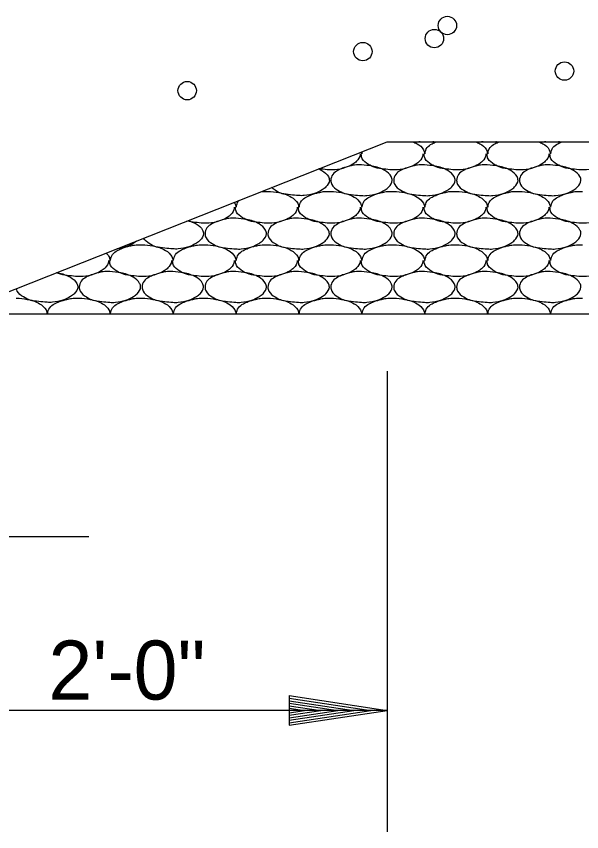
# Model space of a CAD drawing. Extents: x 3287 to 1767681, y -265 to 581440.
# Drawn here: x 3331.47 to 3342.97, y -60.82 to -44.23 of the extents above; entities that cross this region are included whole.
import ezdxf

# ---------------------------------------------------------------- set-up
doc = ezdxf.new("R2010")
doc.units = 0
doc.layers.add('Default', color=7, linetype='Continuous')

msp = doc.modelspace()

# ---------------------------------------------------------------- linework, layer by layer
at = {"layer": 'Default'}
for p, q in [((3329.016, -50.743), (3339.016, -46.785)), ((3339.016, -46.785), (3419.01, -46.785)), ((3336.461, -47.796), (3336.574, -47.795)), ((3336.574, -47.795), (3336.589, -47.795)), ((3337.854, -47.795), (3337.869, -47.795)), ((3339.133, -47.795), (3339.148, -47.795)), ((3340.413, -47.795), (3340.428, -47.795)), ((3341.693, -47.795), (3341.708, -47.795)), ((3342.973, -47.795), (3342.988, -47.795)), ((3334.014, -48.88), (3334.029, -48.88)), ((3335.294, -48.88), (3335.309, -48.88)), ((3336.574, -48.88), (3336.589, -48.88)), ((3337.854, -48.88), (3337.869, -48.88)), ((3339.133, -48.88), (3339.148, -48.88)), ((3340.413, -48.88), (3340.428, -48.88)), ((3341.693, -48.88), (3341.708, -48.88)), ((3342.973, -48.88), (3342.988, -48.88)), ((3332.734, -49.965), (3332.749, -49.965)), ((3334.014, -49.965), (3334.029, -49.965)), ((3335.294, -49.965), (3335.309, -49.965)), ((3336.574, -49.965), (3336.589, -49.965)), ((3337.854, -49.965), (3337.869, -49.965)), ((3339.133, -49.965), (3339.148, -49.965)), ((3340.413, -49.965), (3340.428, -49.965)), ((3341.693, -49.965), (3341.708, -49.965)), ((3342.973, -49.965), (3342.988, -49.965)), ((3330.174, -50.285), (3419.01, -50.285)), ((3339.016, -51.45), (3339.016, -60.817)), ((3332.947, -54.819), (3329.016, -54.819)), ((3337.018, -58.05), (3339.018, -58.35)), ((3337.018, -58.05), (3337.018, -58.65)), ((3337.018, -58.1), (3338.683, -58.35)), ((3337.018, -58.155), (3338.338, -58.35)), ((3337.018, -58.205), (3338.008, -58.35)), ((3339.016, -58.352), (3329.016, -58.352)), ((3337.018, -58.255), (3337.668, -58.35)), ((3337.018, -58.305), (3337.333, -58.35)), ((3337.018, -58.65), (3339.018, -58.35)), ((3337.018, -58.45), (3337.668, -58.35)), ((3337.018, -58.55), (3338.338, -58.35)), ((3337.018, -58.6), (3338.683, -58.35)), ((3337.018, -58.5), (3338.008, -58.35)), ((3337.018, -58.4), (3337.333, -58.35))]:
    msp.add_line(p, q, dxfattribs=at)
for centre in [(3340.24, -44.421), (3339.976, -44.686), (3338.52, -44.951), (3342.623, -45.348), (3334.946, -45.746)]:
    msp.add_circle(centre, 0.187, dxfattribs=at)
for points in [[(3339.538, -46.785), (3339.623, -46.825), (3339.753, -46.95), (3339.773, -47.025), (3339.773, -47.03)], [(3339.963, -46.785), (3339.883, -46.795), (3339.773, -46.795), (3339.656, -46.785)], [(3339.788, -47.03), (3339.788, -47.025), (3339.828, -46.905), (3339.928, -46.825), (3340.014, -46.785)], [(3340.818, -46.785), (3340.903, -46.825), (3341.033, -46.95), (3341.053, -47.025), (3341.053, -47.03)], [(3341.243, -46.785), (3341.163, -46.795), (3341.053, -46.795), (3340.936, -46.785)], [(3341.068, -47.03), (3341.068, -47.025), (3341.108, -46.905), (3341.208, -46.825), (3341.294, -46.785)], [(3342.098, -46.785), (3342.183, -46.825), (3342.313, -46.95), (3342.333, -47.025), (3342.333, -47.03)], [(3342.523, -46.785), (3342.443, -46.795), (3342.333, -46.795), (3342.216, -46.785)], [(3342.348, -47.03), (3342.348, -47.025), (3342.388, -46.905), (3342.488, -46.825), (3342.574, -46.785)], [(3338.463, -47.03), (3338.463, -47.045), (3338.393, -47.18), (3338.318, -47.24), (3338.163, -47.31), (3337.949, -47.355), (3337.854, -47.355)], [(3339.133, -47.355), (3339.113, -47.355), (3338.948, -47.34), (3338.768, -47.31), (3338.633, -47.245), (3338.508, -47.13), (3338.488, -47.045), (3338.488, -47.03)], [(3338.489, -46.993), (3338.493, -47.025), (3338.493, -47.03)], [(3338.508, -47.03), (3338.508, -47.025), (3338.513, -46.984)], [(3339.743, -47.03), (3339.743, -47.045), (3339.673, -47.18), (3339.598, -47.24), (3339.443, -47.31), (3339.228, -47.355), (3339.133, -47.355)], [(3340.413, -47.355), (3340.393, -47.355), (3340.228, -47.34), (3340.048, -47.31), (3339.913, -47.245), (3339.788, -47.13), (3339.768, -47.045), (3339.768, -47.03)], [(3341.023, -47.03), (3341.023, -47.045), (3340.953, -47.18), (3340.878, -47.24), (3340.723, -47.31), (3340.508, -47.355), (3340.413, -47.355)], [(3341.693, -47.355), (3341.673, -47.355), (3341.508, -47.34), (3341.328, -47.31), (3341.193, -47.245), (3341.068, -47.13), (3341.048, -47.045), (3341.048, -47.03)], [(3342.303, -47.03), (3342.303, -47.045), (3342.233, -47.18), (3342.158, -47.24), (3342.003, -47.31), (3341.788, -47.355), (3341.693, -47.355)], [(3342.973, -47.355), (3342.953, -47.355), (3342.788, -47.34), (3342.608, -47.31), (3342.473, -47.245), (3342.348, -47.13), (3342.328, -47.045), (3342.328, -47.03)], [(3343.583, -47.03), (3343.583, -47.045), (3343.513, -47.18), (3343.438, -47.24), (3343.283, -47.31), (3343.068, -47.355), (3342.973, -47.355)], [(3338.493, -47.255), (3338.713, -47.28), (3338.968, -47.37), (3339.098, -47.495), (3339.118, -47.57), (3339.048, -47.705), (3338.973, -47.765), (3338.818, -47.835), (3338.603, -47.88), (3338.493, -47.88), (3338.328, -47.865), (3338.148, -47.835), (3338.014, -47.77), (3337.889, -47.655), (3337.869, -47.57), (3337.909, -47.45), (3338.009, -47.37), (3338.108, -47.325), (3338.258, -47.28), (3338.353, -47.26), (3338.493, -47.255)], [(3339.773, -47.255), (3339.993, -47.28), (3340.248, -47.37), (3340.378, -47.495), (3340.398, -47.57), (3340.328, -47.705), (3340.253, -47.765), (3340.098, -47.835), (3339.883, -47.88), (3339.773, -47.88), (3339.608, -47.865), (3339.428, -47.835), (3339.293, -47.77), (3339.168, -47.655), (3339.148, -47.57), (3339.188, -47.45), (3339.288, -47.37), (3339.388, -47.325), (3339.538, -47.28), (3339.633, -47.26), (3339.773, -47.255)], [(3341.053, -47.255), (3341.273, -47.28), (3341.528, -47.37), (3341.658, -47.495), (3341.678, -47.57), (3341.608, -47.705), (3341.533, -47.765), (3341.378, -47.835), (3341.163, -47.88), (3341.053, -47.88), (3340.888, -47.865), (3340.708, -47.835), (3340.573, -47.77), (3340.448, -47.655), (3340.428, -47.57), (3340.468, -47.45), (3340.568, -47.37), (3340.668, -47.325), (3340.818, -47.28), (3340.913, -47.26), (3341.053, -47.255)], [(3342.333, -47.255), (3342.553, -47.28), (3342.808, -47.37), (3342.938, -47.495), (3342.958, -47.57), (3342.888, -47.705), (3342.813, -47.765), (3342.658, -47.835), (3342.443, -47.88), (3342.333, -47.88), (3342.168, -47.865), (3341.988, -47.835), (3341.853, -47.77), (3341.728, -47.655), (3341.708, -47.57), (3341.748, -47.45), (3341.848, -47.37), (3341.948, -47.325), (3342.098, -47.28), (3342.193, -47.26), (3342.333, -47.255)], [(3337.62, -47.337), (3337.689, -47.37), (3337.819, -47.495), (3337.839, -47.57), (3337.769, -47.705), (3337.694, -47.765), (3337.539, -47.835), (3337.324, -47.88), (3337.214, -47.88), (3337.049, -47.865), (3336.869, -47.835), (3336.734, -47.77), (3336.661, -47.717)], [(3337.854, -47.355), (3337.834, -47.355), (3337.669, -47.34), (3337.626, -47.335)], [(3336.589, -47.795), (3336.809, -47.82), (3337.064, -47.91), (3337.194, -48.035), (3337.214, -48.11), (3337.214, -48.115)], [(3337.229, -48.115), (3337.229, -48.11), (3337.269, -47.99), (3337.369, -47.91), (3337.469, -47.865), (3337.619, -47.82), (3337.714, -47.8), (3337.854, -47.795)], [(3337.869, -47.795), (3338.089, -47.82), (3338.343, -47.91), (3338.473, -48.035), (3338.493, -48.11), (3338.493, -48.115)], [(3338.508, -48.115), (3338.508, -48.11), (3338.548, -47.99), (3338.648, -47.91), (3338.748, -47.865), (3338.898, -47.82), (3338.993, -47.8), (3339.133, -47.795)], [(3339.148, -47.795), (3339.368, -47.82), (3339.623, -47.91), (3339.753, -48.035), (3339.773, -48.11), (3339.773, -48.115)], [(3339.788, -48.115), (3339.788, -48.11), (3339.828, -47.99), (3339.928, -47.91), (3340.028, -47.865), (3340.178, -47.82), (3340.273, -47.8), (3340.413, -47.795)], [(3340.428, -47.795), (3340.648, -47.82), (3340.903, -47.91), (3341.033, -48.035), (3341.053, -48.11), (3341.053, -48.115)], [(3341.068, -48.115), (3341.068, -48.11), (3341.108, -47.99), (3341.208, -47.91), (3341.308, -47.865), (3341.458, -47.82), (3341.553, -47.8), (3341.693, -47.795)], [(3341.708, -47.795), (3341.928, -47.82), (3342.183, -47.91), (3342.313, -48.035), (3342.333, -48.11), (3342.333, -48.115)], [(3342.348, -48.115), (3342.348, -48.11), (3342.388, -47.99), (3342.488, -47.91), (3342.588, -47.865), (3342.738, -47.82), (3342.833, -47.8), (3342.973, -47.795)], [(3335.903, -48.017), (3335.914, -48.035), (3335.934, -48.11), (3335.934, -48.115)], [(3335.949, -48.115), (3335.949, -48.11), (3335.989, -47.99), (3335.996, -47.98)], [(3335.904, -48.115), (3335.904, -48.13), (3335.834, -48.265), (3335.759, -48.325), (3335.604, -48.395), (3335.389, -48.44), (3335.294, -48.44)], [(3336.574, -48.44), (3336.554, -48.44), (3336.389, -48.425), (3336.209, -48.395), (3336.074, -48.33), (3335.949, -48.215), (3335.929, -48.13), (3335.929, -48.115)], [(3337.184, -48.115), (3337.184, -48.13), (3337.114, -48.265), (3337.039, -48.325), (3336.884, -48.395), (3336.669, -48.44), (3336.574, -48.44)], [(3337.854, -48.44), (3337.834, -48.44), (3337.669, -48.425), (3337.489, -48.395), (3337.354, -48.33), (3337.229, -48.215), (3337.209, -48.13), (3337.209, -48.115)], [(3338.463, -48.115), (3338.463, -48.13), (3338.393, -48.265), (3338.318, -48.325), (3338.163, -48.395), (3337.949, -48.44), (3337.854, -48.44)], [(3339.133, -48.44), (3339.113, -48.44), (3338.948, -48.425), (3338.768, -48.395), (3338.633, -48.33), (3338.508, -48.215), (3338.488, -48.13), (3338.488, -48.115)], [(3339.743, -48.115), (3339.743, -48.13), (3339.673, -48.265), (3339.598, -48.325), (3339.443, -48.395), (3339.228, -48.44), (3339.133, -48.44)], [(3340.413, -48.44), (3340.393, -48.44), (3340.228, -48.425), (3340.048, -48.395), (3339.913, -48.33), (3339.788, -48.215), (3339.768, -48.13), (3339.768, -48.115)], [(3341.023, -48.115), (3341.023, -48.13), (3340.953, -48.265), (3340.878, -48.325), (3340.723, -48.395), (3340.508, -48.44), (3340.413, -48.44)], [(3341.693, -48.44), (3341.673, -48.44), (3341.508, -48.425), (3341.328, -48.395), (3341.193, -48.33), (3341.068, -48.215), (3341.048, -48.13), (3341.048, -48.115)], [(3342.303, -48.115), (3342.303, -48.13), (3342.233, -48.265), (3342.158, -48.325), (3342.003, -48.395), (3341.788, -48.44), (3341.693, -48.44)], [(3342.973, -48.44), (3342.953, -48.44), (3342.788, -48.425), (3342.608, -48.395), (3342.473, -48.33), (3342.348, -48.215), (3342.328, -48.13), (3342.328, -48.115)], [(3343.583, -48.115), (3343.583, -48.13), (3343.513, -48.265), (3343.438, -48.325), (3343.283, -48.395), (3343.068, -48.44), (3342.973, -48.44)], [(3334.966, -48.388), (3335.129, -48.455), (3335.259, -48.58), (3335.279, -48.655), (3335.209, -48.79), (3335.134, -48.85), (3334.979, -48.92), (3334.764, -48.965), (3334.654, -48.965), (3334.489, -48.95), (3334.309, -48.92), (3334.174, -48.855), (3334.055, -48.749)], [(3335.294, -48.44), (3335.274, -48.44), (3335.109, -48.425), (3334.941, -48.398)], [(3335.934, -48.34), (3336.154, -48.365), (3336.409, -48.455), (3336.539, -48.58), (3336.559, -48.655), (3336.489, -48.79), (3336.414, -48.85), (3336.259, -48.92), (3336.044, -48.965), (3335.934, -48.965), (3335.769, -48.95), (3335.589, -48.92), (3335.454, -48.855), (3335.329, -48.74), (3335.309, -48.655), (3335.349, -48.535), (3335.449, -48.455), (3335.549, -48.41), (3335.699, -48.365), (3335.794, -48.345), (3335.934, -48.34)], [(3337.214, -48.34), (3337.434, -48.365), (3337.689, -48.455), (3337.819, -48.58), (3337.839, -48.655), (3337.769, -48.79), (3337.694, -48.85), (3337.539, -48.92), (3337.324, -48.965), (3337.214, -48.965), (3337.049, -48.95), (3336.869, -48.92), (3336.734, -48.855), (3336.609, -48.74), (3336.589, -48.655), (3336.629, -48.535), (3336.729, -48.455), (3336.829, -48.41), (3336.979, -48.365), (3337.074, -48.345), (3337.214, -48.34)], [(3338.493, -48.34), (3338.713, -48.365), (3338.968, -48.455), (3339.098, -48.58), (3339.118, -48.655), (3339.048, -48.79), (3338.973, -48.85), (3338.818, -48.92), (3338.603, -48.965), (3338.493, -48.965), (3338.328, -48.95), (3338.148, -48.92), (3338.014, -48.855), (3337.889, -48.74), (3337.869, -48.655), (3337.909, -48.535), (3338.009, -48.455), (3338.108, -48.41), (3338.258, -48.365), (3338.353, -48.345), (3338.493, -48.34)], [(3339.773, -48.34), (3339.993, -48.365), (3340.248, -48.455), (3340.378, -48.58), (3340.398, -48.655), (3340.328, -48.79), (3340.253, -48.85), (3340.098, -48.92), (3339.883, -48.965), (3339.773, -48.965), (3339.608, -48.95), (3339.428, -48.92), (3339.293, -48.855), (3339.168, -48.74), (3339.148, -48.655), (3339.188, -48.535), (3339.288, -48.455), (3339.388, -48.41), (3339.538, -48.365), (3339.633, -48.345), (3339.773, -48.34)], [(3341.053, -48.34), (3341.273, -48.365), (3341.528, -48.455), (3341.658, -48.58), (3341.678, -48.655), (3341.608, -48.79), (3341.533, -48.85), (3341.378, -48.92), (3341.163, -48.965), (3341.053, -48.965), (3340.888, -48.95), (3340.708, -48.92), (3340.573, -48.855), (3340.448, -48.74), (3340.428, -48.655), (3340.468, -48.535), (3340.568, -48.455), (3340.668, -48.41), (3340.818, -48.365), (3340.913, -48.345), (3341.053, -48.34)], [(3342.333, -48.34), (3342.553, -48.365), (3342.808, -48.455), (3342.938, -48.58), (3342.958, -48.655), (3342.888, -48.79), (3342.813, -48.85), (3342.658, -48.92), (3342.443, -48.965), (3342.333, -48.965), (3342.168, -48.95), (3341.988, -48.92), (3341.853, -48.855), (3341.728, -48.74), (3341.708, -48.655), (3341.748, -48.535), (3341.848, -48.455), (3341.948, -48.41), (3342.098, -48.365), (3342.193, -48.345), (3342.333, -48.34)], [(3333.389, -49.2), (3333.389, -49.195), (3333.429, -49.075), (3333.529, -48.995), (3333.629, -48.95), (3333.779, -48.905), (3333.874, -48.885), (3334.014, -48.88)], [(3333.916, -48.804), (3333.854, -48.85), (3333.699, -48.92), (3333.516, -48.962)], [(3334.029, -48.88), (3334.249, -48.905), (3334.504, -48.995), (3334.634, -49.12), (3334.654, -49.195), (3334.654, -49.2)], [(3334.669, -49.2), (3334.669, -49.195), (3334.709, -49.075), (3334.809, -48.995), (3334.909, -48.95), (3335.059, -48.905), (3335.154, -48.885), (3335.294, -48.88)], [(3335.309, -48.88), (3335.529, -48.905), (3335.784, -48.995), (3335.914, -49.12), (3335.934, -49.195), (3335.934, -49.2)], [(3335.949, -49.2), (3335.949, -49.195), (3335.989, -49.075), (3336.089, -48.995), (3336.189, -48.95), (3336.339, -48.905), (3336.434, -48.885), (3336.574, -48.88)], [(3336.589, -48.88), (3336.809, -48.905), (3337.064, -48.995), (3337.194, -49.12), (3337.214, -49.195), (3337.214, -49.2)], [(3337.229, -49.2), (3337.229, -49.195), (3337.269, -49.075), (3337.369, -48.995), (3337.469, -48.95), (3337.619, -48.905), (3337.714, -48.885), (3337.854, -48.88)], [(3337.869, -48.88), (3338.089, -48.905), (3338.343, -48.995), (3338.473, -49.12), (3338.493, -49.195), (3338.493, -49.2)], [(3338.508, -49.2), (3338.508, -49.195), (3338.548, -49.075), (3338.648, -48.995), (3338.748, -48.95), (3338.898, -48.905), (3338.993, -48.885), (3339.133, -48.88)], [(3339.148, -48.88), (3339.368, -48.905), (3339.623, -48.995), (3339.753, -49.12), (3339.773, -49.195), (3339.773, -49.2)], [(3339.788, -49.2), (3339.788, -49.195), (3339.828, -49.075), (3339.928, -48.995), (3340.028, -48.95), (3340.178, -48.905), (3340.273, -48.885), (3340.413, -48.88)], [(3340.428, -48.88), (3340.648, -48.905), (3340.903, -48.995), (3341.033, -49.12), (3341.053, -49.195), (3341.053, -49.2)], [(3341.068, -49.2), (3341.068, -49.195), (3341.108, -49.075), (3341.208, -48.995), (3341.308, -48.95), (3341.458, -48.905), (3341.553, -48.885), (3341.693, -48.88)], [(3341.708, -48.88), (3341.928, -48.905), (3342.183, -48.995), (3342.313, -49.12), (3342.333, -49.195), (3342.333, -49.2)], [(3342.348, -49.2), (3342.348, -49.195), (3342.388, -49.075), (3342.488, -48.995), (3342.588, -48.95), (3342.738, -48.905), (3342.833, -48.885), (3342.973, -48.88)], [(3333.299, -49.048), (3333.354, -49.12), (3333.374, -49.195), (3333.374, -49.2)], [(3333.344, -49.2), (3333.344, -49.215), (3333.274, -49.35), (3333.199, -49.41), (3333.044, -49.48), (3332.829, -49.525), (3332.734, -49.525)], [(3334.014, -49.525), (3333.994, -49.525), (3333.829, -49.51), (3333.649, -49.48), (3333.514, -49.415), (3333.389, -49.3), (3333.369, -49.215), (3333.369, -49.2)], [(3334.624, -49.2), (3334.624, -49.215), (3334.554, -49.35), (3334.479, -49.41), (3334.324, -49.48), (3334.109, -49.525), (3334.014, -49.525)], [(3335.294, -49.525), (3335.274, -49.525), (3335.109, -49.51), (3334.929, -49.48), (3334.794, -49.415), (3334.669, -49.3), (3334.649, -49.215), (3334.649, -49.2)], [(3335.904, -49.2), (3335.904, -49.215), (3335.834, -49.35), (3335.759, -49.41), (3335.604, -49.48), (3335.389, -49.525), (3335.294, -49.525)], [(3336.574, -49.525), (3336.554, -49.525), (3336.389, -49.51), (3336.209, -49.48), (3336.074, -49.415), (3335.949, -49.3), (3335.929, -49.215), (3335.929, -49.2)], [(3337.184, -49.2), (3337.184, -49.215), (3337.114, -49.35), (3337.039, -49.41), (3336.884, -49.48), (3336.669, -49.525), (3336.574, -49.525)], [(3337.854, -49.525), (3337.834, -49.525), (3337.669, -49.51), (3337.489, -49.48), (3337.354, -49.415), (3337.229, -49.3), (3337.209, -49.215), (3337.209, -49.2)], [(3338.463, -49.2), (3338.463, -49.215), (3338.393, -49.35), (3338.318, -49.41), (3338.163, -49.48), (3337.949, -49.525), (3337.854, -49.525)], [(3339.133, -49.525), (3339.113, -49.525), (3338.948, -49.51), (3338.768, -49.48), (3338.633, -49.415), (3338.508, -49.3), (3338.488, -49.215), (3338.488, -49.2)], [(3339.743, -49.2), (3339.743, -49.215), (3339.673, -49.35), (3339.598, -49.41), (3339.443, -49.48), (3339.228, -49.525), (3339.133, -49.525)], [(3340.413, -49.525), (3340.393, -49.525), (3340.228, -49.51), (3340.048, -49.48), (3339.913, -49.415), (3339.788, -49.3), (3339.768, -49.215), (3339.768, -49.2)], [(3341.023, -49.2), (3341.023, -49.215), (3340.953, -49.35), (3340.878, -49.41), (3340.723, -49.48), (3340.508, -49.525), (3340.413, -49.525)], [(3341.693, -49.525), (3341.673, -49.525), (3341.508, -49.51), (3341.328, -49.48), (3341.193, -49.415), (3341.068, -49.3), (3341.048, -49.215), (3341.048, -49.2)], [(3342.303, -49.2), (3342.303, -49.215), (3342.233, -49.35), (3342.158, -49.41), (3342.003, -49.48), (3341.788, -49.525), (3341.693, -49.525)], [(3342.973, -49.525), (3342.953, -49.525), (3342.788, -49.51), (3342.608, -49.48), (3342.473, -49.415), (3342.348, -49.3), (3342.328, -49.215), (3342.328, -49.2)], [(3343.583, -49.2), (3343.583, -49.215), (3343.513, -49.35), (3343.438, -49.41), (3343.283, -49.48), (3343.068, -49.525), (3342.973, -49.525)], [(3332.294, -49.446), (3332.314, -49.45), (3332.569, -49.54), (3332.699, -49.665), (3332.719, -49.74), (3332.649, -49.875), (3332.574, -49.935), (3332.419, -50.005), (3332.204, -50.05), (3332.094, -50.05), (3331.929, -50.035), (3331.749, -50.005), (3331.614, -49.94), (3331.489, -49.825), (3331.47, -49.772)], [(3332.734, -49.525), (3332.714, -49.525), (3332.549, -49.51), (3332.369, -49.48), (3332.289, -49.448)], [(3333.374, -49.425), (3333.594, -49.45), (3333.849, -49.54), (3333.979, -49.665), (3333.999, -49.74), (3333.929, -49.875), (3333.854, -49.935), (3333.699, -50.005), (3333.484, -50.05), (3333.374, -50.05), (3333.209, -50.035), (3333.029, -50.005), (3332.894, -49.94), (3332.769, -49.825), (3332.749, -49.74), (3332.789, -49.62), (3332.889, -49.54), (3332.989, -49.495), (3333.139, -49.45), (3333.234, -49.43), (3333.374, -49.425)], [(3334.654, -49.425), (3334.874, -49.45), (3335.129, -49.54), (3335.259, -49.665), (3335.279, -49.74), (3335.209, -49.875), (3335.134, -49.935), (3334.979, -50.005), (3334.764, -50.05), (3334.654, -50.05), (3334.489, -50.035), (3334.309, -50.005), (3334.174, -49.94), (3334.049, -49.825), (3334.029, -49.74), (3334.069, -49.62), (3334.169, -49.54), (3334.269, -49.495), (3334.419, -49.45), (3334.514, -49.43), (3334.654, -49.425)], [(3335.934, -49.425), (3336.154, -49.45), (3336.409, -49.54), (3336.539, -49.665), (3336.559, -49.74), (3336.489, -49.875), (3336.414, -49.935), (3336.259, -50.005), (3336.044, -50.05), (3335.934, -50.05), (3335.769, -50.035), (3335.589, -50.005), (3335.454, -49.94), (3335.329, -49.825), (3335.309, -49.74), (3335.349, -49.62), (3335.449, -49.54), (3335.549, -49.495), (3335.699, -49.45), (3335.794, -49.43), (3335.934, -49.425)], [(3337.214, -49.425), (3337.434, -49.45), (3337.689, -49.54), (3337.819, -49.665), (3337.839, -49.74), (3337.769, -49.875), (3337.694, -49.935), (3337.539, -50.005), (3337.324, -50.05), (3337.214, -50.05), (3337.049, -50.035), (3336.869, -50.005), (3336.734, -49.94), (3336.609, -49.825), (3336.589, -49.74), (3336.629, -49.62), (3336.729, -49.54), (3336.829, -49.495), (3336.979, -49.45), (3337.074, -49.43), (3337.214, -49.425)], [(3338.493, -49.425), (3338.713, -49.45), (3338.968, -49.54), (3339.098, -49.665), (3339.118, -49.74), (3339.048, -49.875), (3338.973, -49.935), (3338.818, -50.005), (3338.603, -50.05), (3338.493, -50.05), (3338.328, -50.035), (3338.148, -50.005), (3338.014, -49.94), (3337.889, -49.825), (3337.869, -49.74), (3337.909, -49.62), (3338.009, -49.54), (3338.108, -49.495), (3338.258, -49.45), (3338.353, -49.43), (3338.493, -49.425)], [(3339.773, -49.425), (3339.993, -49.45), (3340.248, -49.54), (3340.378, -49.665), (3340.398, -49.74), (3340.328, -49.875), (3340.253, -49.935), (3340.098, -50.005), (3339.883, -50.05), (3339.773, -50.05), (3339.608, -50.035), (3339.428, -50.005), (3339.293, -49.94), (3339.168, -49.825), (3339.148, -49.74), (3339.188, -49.62), (3339.288, -49.54), (3339.388, -49.495), (3339.538, -49.45), (3339.633, -49.43), (3339.773, -49.425)], [(3341.053, -49.425), (3341.273, -49.45), (3341.528, -49.54), (3341.658, -49.665), (3341.678, -49.74), (3341.608, -49.875), (3341.533, -49.935), (3341.378, -50.005), (3341.163, -50.05), (3341.053, -50.05), (3340.888, -50.035), (3340.708, -50.005), (3340.573, -49.94), (3340.448, -49.825), (3340.428, -49.74), (3340.468, -49.62), (3340.568, -49.54), (3340.668, -49.495), (3340.818, -49.45), (3340.913, -49.43), (3341.053, -49.425)], [(3342.333, -49.425), (3342.553, -49.45), (3342.808, -49.54), (3342.938, -49.665), (3342.958, -49.74), (3342.888, -49.875), (3342.813, -49.935), (3342.658, -50.005), (3342.443, -50.05), (3342.333, -50.05), (3342.168, -50.035), (3341.988, -50.005), (3341.853, -49.94), (3341.728, -49.825), (3341.708, -49.74), (3341.748, -49.62), (3341.848, -49.54), (3341.948, -49.495), (3342.098, -49.45), (3342.193, -49.43), (3342.333, -49.425)], [(3331.469, -49.965), (3331.689, -49.99), (3331.944, -50.08), (3332.074, -50.205), (3332.094, -50.28), (3332.094, -50.285)], [(3332.109, -50.285), (3332.109, -50.28), (3332.149, -50.16), (3332.249, -50.08), (3332.349, -50.035), (3332.499, -49.99), (3332.594, -49.97), (3332.734, -49.965)], [(3332.749, -49.965), (3332.969, -49.99), (3333.224, -50.08), (3333.354, -50.205), (3333.374, -50.28), (3333.374, -50.285)], [(3333.389, -50.285), (3333.389, -50.28), (3333.429, -50.16), (3333.529, -50.08), (3333.629, -50.035), (3333.779, -49.99), (3333.874, -49.97), (3334.014, -49.965)], [(3334.029, -49.965), (3334.249, -49.99), (3334.504, -50.08), (3334.634, -50.205), (3334.654, -50.28), (3334.654, -50.285)], [(3334.669, -50.285), (3334.669, -50.28), (3334.709, -50.16), (3334.809, -50.08), (3334.909, -50.035), (3335.059, -49.99), (3335.154, -49.97), (3335.294, -49.965)], [(3335.309, -49.965), (3335.529, -49.99), (3335.784, -50.08), (3335.914, -50.205), (3335.934, -50.28), (3335.934, -50.285)], [(3335.949, -50.285), (3335.949, -50.28), (3335.989, -50.16), (3336.089, -50.08), (3336.189, -50.035), (3336.339, -49.99), (3336.434, -49.97), (3336.574, -49.965)], [(3336.589, -49.965), (3336.809, -49.99), (3337.064, -50.08), (3337.194, -50.205), (3337.214, -50.28), (3337.214, -50.285)], [(3337.229, -50.285), (3337.229, -50.28), (3337.269, -50.16), (3337.369, -50.08), (3337.469, -50.035), (3337.619, -49.99), (3337.714, -49.97), (3337.854, -49.965)], [(3337.869, -49.965), (3338.089, -49.99), (3338.343, -50.08), (3338.473, -50.205), (3338.493, -50.28), (3338.493, -50.285)], [(3338.508, -50.285), (3338.508, -50.28), (3338.548, -50.16), (3338.648, -50.08), (3338.748, -50.035), (3338.898, -49.99), (3338.993, -49.97), (3339.133, -49.965)], [(3339.148, -49.965), (3339.368, -49.99), (3339.623, -50.08), (3339.753, -50.205), (3339.773, -50.28), (3339.773, -50.285)], [(3339.788, -50.285), (3339.788, -50.28), (3339.828, -50.16), (3339.928, -50.08), (3340.028, -50.035), (3340.178, -49.99), (3340.273, -49.97), (3340.413, -49.965)], [(3340.428, -49.965), (3340.648, -49.99), (3340.903, -50.08), (3341.033, -50.205), (3341.053, -50.28), (3341.053, -50.285)], [(3341.068, -50.285), (3341.068, -50.28), (3341.108, -50.16), (3341.208, -50.08), (3341.308, -50.035), (3341.458, -49.99), (3341.553, -49.97), (3341.693, -49.965)], [(3341.708, -49.965), (3341.928, -49.99), (3342.183, -50.08), (3342.313, -50.205), (3342.333, -50.28), (3342.333, -50.285)], [(3342.348, -50.285), (3342.348, -50.28), (3342.388, -50.16), (3342.488, -50.08), (3342.588, -50.035), (3342.738, -49.99), (3342.833, -49.97), (3342.973, -49.965)]]:
    msp.add_spline(points, degree=3, dxfattribs=at)

# ---------------------------------------------------------------- texts
msp.add_text('2\'-0"', height=1.2, dxfattribs=at).set_placement((3332.124, -58.13))

doc.saveas('drawing.dxf')
